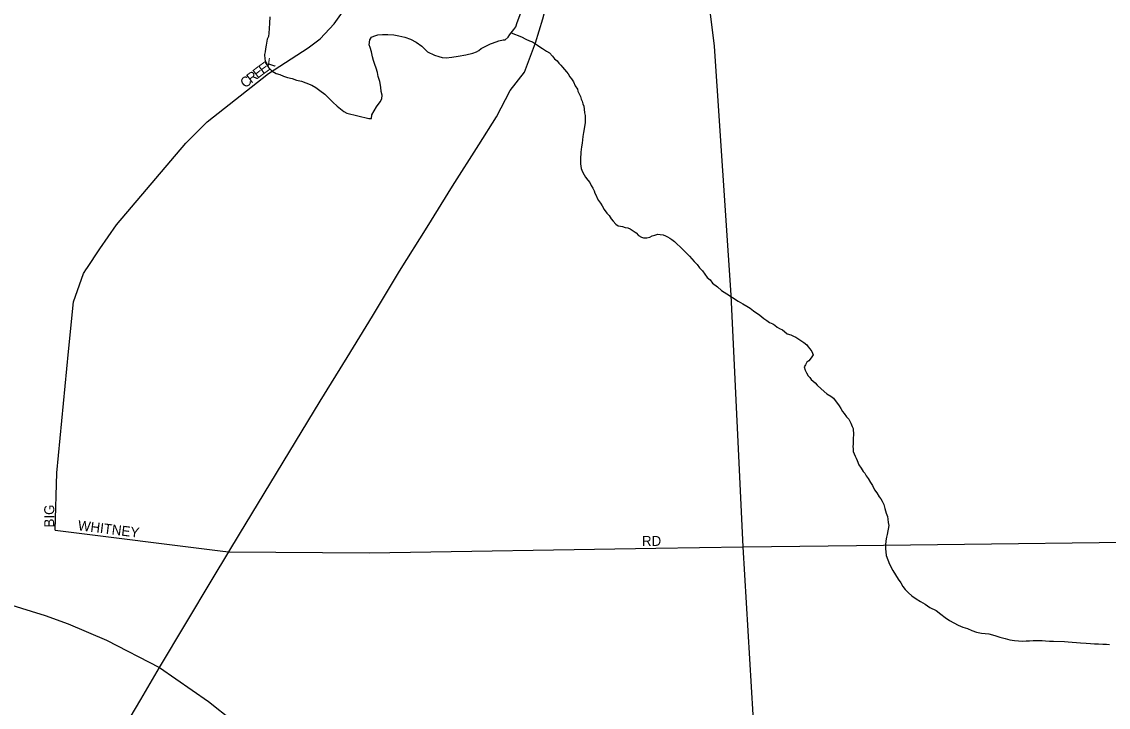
# Model space of a CAD drawing. Extents: x 2010165 to 2382125, y 1060529 to 1407316.
# Drawn here: x 2152412 to 2157848, y 1217745 to 1221171 of the extents above; entities that cross this region are included whole.
import ezdxf

# ---------------------------------------------------------------- set-up
doc = ezdxf.new("R2010")
doc.units = 0
for name, color, linetype in [('GM_X_City_Street', 7, 'Continuous'), ('GM_X_City_Street_Text', 7, 'Continuous'), ('GM_X_Interstate_Route', 7, 'Continuous'), ('GM_X_Minor_River', 7, 'Continuous'), ('GM_X_US_Route', 7, 'Continuous')]:
    doc.layers.add(name, color=color, linetype=linetype)

msp = doc.modelspace()

# ---------------------------------------------------------------- linework, layer by layer
at = {"layer": 'GM_X_City_Street'}
for points in [[(2152738.1, 1219937.6), (2152803.6, 1220035.7), (2152886.6, 1220156.5), (2153233.2, 1220564.9), (2153340.3, 1220671.2), (2153646.2, 1220911.7), (2153845.1, 1221039.9), (2153906, 1221085.1), (2153976, 1221160.9), (2154034.4, 1221242.5), (2154060.6, 1221283.7), (2154063, 1221287.6)], [(2152579.5, 1218629.2), (2152587.6, 1218916.2), (2152646.1, 1219522.6), (2152671.8, 1219771.3), (2152721.9, 1219913.3), (2152736.5, 1219935.2), (2152738.1, 1219937.6)], [(2152579.5, 1218629.2), (2153418.6, 1218524.5)], [(2156588.9, 1218553.8), (2158477.6, 1218575.9), (2160599.4, 1218587.6), (2164832.8, 1218637)], [(2153418.6, 1218524.5), (2153448.3, 1218520.8), (2154151.5, 1218516.2), (2155584.9, 1218540)], [(2155584.9, 1218540), (2156021.8, 1218547.2), (2156588.9, 1218553.8)]]:
    msp.add_lwpolyline(points, dxfattribs=at)
at = {"layer": 'GM_X_Interstate_Route'}
for points in [[(2156238, 1214867.8), (2156232.1, 1214967.2), (2156174.3, 1215951.3), (2156131.2, 1216685), (2156123.1, 1216822.9), (2156114.4, 1216971.2), (2156113, 1216994.3), (2156071.2, 1217706.4), (2156021.8, 1218547.2), (2155961.9, 1219804.3), (2155877.8, 1221048.5), (2155838.4, 1221371.7), (2155826.6, 1221456.7)], [(2152340.8, 1218261.4), (2152530, 1218202.9), (2152643.8, 1218161.6), (2152836.7, 1218079.2), (2153102.2, 1217942.6)], [(2153102.2, 1217942.6), (2153346.8, 1217774), (2153469, 1217677.4), (2153574.3, 1217584.9), (2153687.1, 1217473.7), (2153729, 1217425.4), (2153814, 1217330.6), (2153911.1, 1217210.7), (2153972.2, 1217133.3), (2154200.2, 1216818.5), (2154268, 1216719.6), (2154276.3, 1216707.5), (2154779.6, 1215973.6), (2154964.6, 1215718.1), (2155028.7, 1215641), (2155110.2, 1215555.3), (2155211.4, 1215459.1)]]:
    msp.add_lwpolyline(points, dxfattribs=at)
at = {"layer": 'GM_X_Minor_River'}
for points in [[(2153653.1, 1221194.9), (2153651.5, 1221164.8), (2153649.9, 1221136.7), (2153648.2, 1221114.6), (2153646.4, 1221096.5), (2153640.5, 1221084.4), (2153638.7, 1221074.3), (2153634.9, 1221054.2), (2153631.2, 1221036.1), (2153629.4, 1221020.1), (2153627.5, 1221008), (2153627.8, 1220983.9), (2153632, 1220969.9), (2153638.2, 1220960), (2153648.5, 1220940), (2153664.7, 1220924.2), (2153684.9, 1220912.4), (2153703, 1220906.6), (2153721.1, 1220898.8), (2153741.2, 1220893), (2153765.3, 1220887.3), (2153787.5, 1220879.5), (2153811.6, 1220873.8), (2153833.7, 1220866.1), (2153863.9, 1220854.4), (2153884.1, 1220842.6), (2153904.4, 1220826.8), (2153928.6, 1220809), (2153948.9, 1220789.2), (2153969.2, 1220769.4), (2153989.5, 1220749.6), (2154007.7, 1220735.8), (2154023.9, 1220721.9), (2154038.1, 1220714.1), (2154148.6, 1220687.3), (2154162.6, 1220687.5), (2154164.4, 1220705.6), (2154187.9, 1220746), (2154205.6, 1220770.3), (2154213.4, 1220786.4), (2154215.2, 1220804.5), (2154211, 1220822.5), (2154208.7, 1220844.6), (2154204.3, 1220872.6), (2154196, 1220896.6), (2154191.7, 1220916.6), (2154185.4, 1220938.6), (2154179.2, 1220956.6), (2154172.9, 1220976.6), (2154166.6, 1220996.5), (2154162.3, 1221020.6), (2154156, 1221042.6), (2154149.8, 1221056.5), (2154153.5, 1221080.7), (2154161.3, 1221094.8), (2154173.3, 1221098.9), (2154193.2, 1221105.2), (2154217.3, 1221107.5), (2154243.3, 1221107.8)], [(2154243.3, 1221107.8), (2154273.4, 1221106.2), (2154299.5, 1221100.5), (2154329.6, 1221094.8), (2154357.8, 1221083.2), (2154386, 1221069.5), (2154414.3, 1221049.7), (2154442.8, 1221020), (2154477, 1221004.4), (2154499.2, 1220996.6), (2154515.3, 1220992.8), (2154535.3, 1220991), (2154563.3, 1220993.4), (2154595.3, 1220999.8), (2154633.3, 1221006.3), (2154669.2, 1221014.7), (2154687.2, 1221021), (2154699.1, 1221027.1), (2154711, 1221037.3), (2154756.8, 1221059.9), (2154766.8, 1221064.1), (2154798.7, 1221076.5), (2154820.6, 1221080.8), (2154830.7, 1221080.9), (2154846.5, 1221093.2), (2154854.4, 1221107.3), (2154874.1, 1221131.6), (2154883.9, 1221145.8), (2154891.6, 1221167.9), (2154909, 1221216.3)], [(2154860.9, 1221115.3), (2154912.6, 1221096), (2154934.8, 1221084.2), (2154952.9, 1221076.4), (2154967, 1221070.6), (2154977.1, 1221064.7), (2154993.3, 1221054.8), (2155003.4, 1221044.9), (2155017.6, 1221037.1), (2155027.6, 1221031.2), (2155037.8, 1221023.3), (2155051.9, 1221015.4), (2155068.1, 1220999.6), (2155078.3, 1220985.6), (2155090.5, 1220975.8), (2155098.7, 1220963.8), (2155108.8, 1220953.9), (2155116.9, 1220944), (2155127.1, 1220932.1), (2155137.3, 1220920.1), (2155145.4, 1220910.2), (2155153.6, 1220896.3), (2155161.8, 1220886.3), (2155172, 1220870.4), (2155180.3, 1220850.4), (2155192.5, 1220834.6), (2155194.6, 1220824.5), (2155200.8, 1220810.6), (2155207, 1220796.6), (2155211.2, 1220784.6), (2155215.3, 1220774.6), (2155219.5, 1220760.6), (2155223.7, 1220748.6), (2155225.9, 1220734.6), (2155228.1, 1220716.6), (2155230.3, 1220702.6), (2155230.4, 1220692.6), (2155230.6, 1220680.5), (2155230.8, 1220666.5), (2155223.4, 1220618.2), (2155219.6, 1220598.1), (2155217.9, 1220580), (2155216.1, 1220564), (2155212.3, 1220545.9), (2155210.5, 1220531.8), (2155208.6, 1220519.7), (2155208.8, 1220507.7), (2155207, 1220495.6), (2155207.2, 1220479.6), (2155207.4, 1220461.5), (2155209.6, 1220449.5), (2155211.7, 1220437.5), (2155217.9, 1220421.5), (2155226.2, 1220405.6), (2155232.3, 1220393.6), (2155244.5, 1220379.7), (2155254.7, 1220367.8), (2155260.9, 1220351.8), (2155269.1, 1220339.9), (2155275.3, 1220325.9), (2155279.4, 1220313.9), (2155285.6, 1220302), (2155291.8, 1220290), (2155298, 1220278), (2155308.1, 1220264.1), (2155316.3, 1220250.2), (2155326.6, 1220232.2), (2155338.9, 1220214.3), (2155351, 1220202.4), (2155361.3, 1220186.5), (2155371.4, 1220174.6), (2155383.7, 1220158.7), (2155395.8, 1220150.8), (2155407.8, 1220149), (2155417.9, 1220147.1), (2155431.9, 1220143.2), (2155444, 1220141.4), (2155456.1, 1220135.5), (2155486.4, 1220115.8), (2155498.6, 1220101.9), (2155512.7, 1220094.1), (2155522.8, 1220090.2), (2155538.8, 1220090.4), (2155554.8, 1220094.6), (2155566.7, 1220100.8), (2155578.7, 1220104.9), (2155594.7, 1220109.1), (2155606.7, 1220107.3), (2155620.8, 1220105.4), (2155632.8, 1220101.6), (2155642.9, 1220095.7), (2155655, 1220089.8), (2155665.1, 1220081.9), (2155677.3, 1220072), (2155691.5, 1220060.1), (2155705.7, 1220046.3), (2155723.9, 1220028.4), (2155740.2, 1220012.6), (2155752.4, 1219998.7), (2155764.6, 1219986.8), (2155776.8, 1219972.9)], [(2155776.8, 1219972.9), (2155791, 1219957), (2155803.2, 1219941.1), (2155817.5, 1219925.2), (2155829.7, 1219909.3), (2155841.9, 1219893.4), (2155856.1, 1219881.6), (2155868.4, 1219863.7), (2155892.6, 1219845.9), (2155912.9, 1219828.1), (2155939.2, 1219810.4), (2155967.4, 1219792.6), (2155995.7, 1219774.9), (2156019.9, 1219761.2), (2156040.1, 1219749.4), (2156056.3, 1219739.6), (2156072.5, 1219725.7), (2156104.8, 1219704), (2156125.1, 1219688.2), (2156139.2, 1219678.4), (2156153.4, 1219668.5), (2156169.5, 1219660.7), (2156179.6, 1219654.8), (2156191.8, 1219644.9), (2156203.9, 1219637), (2156218, 1219631.2), (2156228.1, 1219623.3), (2156242.3, 1219611.4), (2156260.4, 1219605.6), (2156272.5, 1219599.8), (2156284.6, 1219593.9), (2156294.7, 1219588), (2156314.9, 1219574.2), (2156325, 1219568.3), (2156339.2, 1219556.4), (2156347.3, 1219546.5), (2156355.5, 1219536.6), (2156365.7, 1219522.6), (2156371.9, 1219506.7), (2156362.1, 1219490.5), (2156350.2, 1219476.3), (2156340.3, 1219470.2), (2156332.5, 1219456), (2156326.6, 1219445.9), (2156330.8, 1219429.9), (2156339, 1219416), (2156347.2, 1219402), (2156355.3, 1219392.1), (2156361.5, 1219382.1), (2156381.7, 1219366.3), (2156391.9, 1219354.4), (2156412.2, 1219336.6), (2156440.6, 1219310.9), (2156460.7, 1219299.1), (2156472.9, 1219289.2), (2156501.4, 1219251.4), (2156509.6, 1219237.5), (2156517.8, 1219223.5), (2156526, 1219213.6), (2156538.2, 1219195.7), (2156550.4, 1219183.8), (2156554.5, 1219173.8), (2156560.7, 1219163.9), (2156566.9, 1219147.9), (2156571, 1219137.9), (2156571.2, 1219127.9), (2156573.3, 1219115.9), (2156573.5, 1219103.8), (2156571.6, 1219091.8), (2156571.9, 1219075.7), (2156572.1, 1219059.7), (2156570.2, 1219047.6), (2156572.4, 1219035.6), (2156572.5, 1219023.6), (2156576.7, 1219011.6), (2156580.9, 1218999.6), (2156587, 1218989.6), (2156591.2, 1218977.6), (2156599.5, 1218955.7), (2156611.7, 1218939.8), (2156621.9, 1218923.8), (2156630.1, 1218913.9), (2156636.2, 1218901.9), (2156646.4, 1218888), (2156658.7, 1218868.1), (2156668.9, 1218852.2), (2156679.2, 1218832.2), (2156689.4, 1218816.3), (2156701.7, 1218796.4), (2156709.9, 1218786.5), (2156716, 1218774.5), (2156724.3, 1218758.6), (2156730.5, 1218738.6), (2156736.9, 1218714.6), (2156743.1, 1218698.6), (2156745.3, 1218684.6), (2156747.5, 1218668.6), (2156749.7, 1218652.5), (2156742.3, 1218608.3), (2156738.4, 1218594.2), (2156734.7, 1218576.1)], [(2156734.7, 1218576.1), (2156732.9, 1218554), (2156733.2, 1218538), (2156737.6, 1218503.9), (2156745.9, 1218481.9), (2156754.2, 1218460), (2156770.7, 1218428.1), (2156783, 1218406.1), (2156797.3, 1218384.2), (2156809.5, 1218366.3), (2156819.8, 1218348.4), (2156832, 1218332.5), (2156848.2, 1218316.6), (2156864.5, 1218300.8), (2156886.7, 1218287), (2156908.9, 1218273.2), (2156931.1, 1218259.5), (2156955.4, 1218243.7), (2156987.6, 1218228.1), (2157009.9, 1218210.3), (2157032.2, 1218192.5), (2157054.4, 1218178.7), (2157074.6, 1218166.9), (2157096.8, 1218155.2), (2157121, 1218145.4), (2157143.1, 1218137.7), (2157165.3, 1218127.9), (2157189.4, 1218120.2), (2157213.5, 1218114.5), (2157249.6, 1218110.9), (2157279.8, 1218103.2), (2157305.9, 1218095.5), (2157332.1, 1218087.8), (2157356.2, 1218082.1), (2157378.3, 1218078.3), (2157398.3, 1218076.6), (2157416.4, 1218074.8), (2157436.4, 1218077.1), (2157454.4, 1218077.3), (2157472.4, 1218077.5), (2157494.5, 1218077.8), (2157516.5, 1218078), (2157534.6, 1218076.2), (2157554.6, 1218074.5), (2157574.7, 1218074.7), (2157628.8, 1218073.4), (2157646.8, 1218071.6), (2157666.9, 1218069.8), (2157688.9, 1218068.1), (2157709, 1218066.3), (2157737.1, 1218064.7), (2157759.1, 1218062.9), (2157779.2, 1218061.2), (2157799.2, 1218061.4), (2157821.3, 1218059.7), (2157839.3, 1218059.9), (2157853.4, 1218058.1)]]:
    msp.add_lwpolyline(points, dxfattribs=at)
at = {"layer": 'GM_X_US_Route'}
for points in [[(2153501.8, 1218609.2), (2153904.9, 1219274.9), (2154040.1, 1219492), (2154167.4, 1219699.1), (2154302.6, 1219924.3), (2154439.9, 1220143.5), (2154567.2, 1220348.6), (2154698.4, 1220555.7), (2154788, 1220696.5), (2154855.5, 1220827.2), (2154926.8, 1220918.5), (2154983.2, 1221065.7), (2155019.7, 1221185.8), (2155045.8, 1221289.2), (2155054.5, 1221337.5)], [(2153365.5, 1218382.5), (2153448.3, 1218520.8), (2153501.8, 1218609.2)], [(2153007.4, 1217782.8), (2153102.2, 1217942.6), (2153365.5, 1218382.5)], [(2152637.2, 1217159.2), (2152651.2, 1217182.1), (2153007.4, 1217782.8)]]:
    msp.add_lwpolyline(points, dxfattribs=at)

# ---------------------------------------------------------------- texts
at = {"layer": 'GM_X_City_Street_Text'}
for s, rotation, p in [('E', 37.2015, (2153592, 1220884.9)), ('E', 35.8807, (2153619.8, 1220906)), ('K', 34.0053, (2153648, 1220926.4)), ('C', 37.1954, (2153529, 1220837.1)), ('R', 37.1941, (2153560.5, 1220861)), ('BIG', 90, (2152574.9, 1218642.8)), ('WHITNEY', 352.8758, (2152691, 1218630.1)), ('RD', 0, (2155514.7, 1218551))]:
    msp.add_text(s, height=50, rotation=rotation, dxfattribs=at).set_placement(p)

doc.saveas('drawing.dxf')
